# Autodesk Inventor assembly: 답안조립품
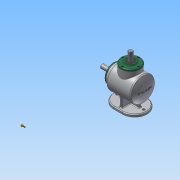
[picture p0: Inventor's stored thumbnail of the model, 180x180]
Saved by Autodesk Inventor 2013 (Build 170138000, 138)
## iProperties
Created: 2016-04
Part Number: 답안조립품
Document SubType Name: Assembly
Designer: Administrator
Author: Administrator
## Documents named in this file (14)
- C:\Users\Administrator\Desktop\460407V1006\답안조립품.iam
- C:\Users\Administrator\Desktop\460407V1006\M4.ipt
- C:\Users\Administrator\Desktop\460407V1006\메인 베벨기어.ipt
- C:\Users\Administrator\Desktop\460407V1006\메인 축.ipt
- 메인 축.ipt
- C:\Users\Administrator\Desktop\460407V1006\베어링 6203.ipt
- C:\Users\Administrator\Desktop\460407V1006\본체.ipt
- C:\Users\Administrator\Desktop\460407V1006\서브 베벨기어.ipt
- C:\Users\Administrator\Desktop\460407V1006\서브 축.ipt
- 서브 축.ipt
- C:\Users\Administrator\Desktop\460407V1006\오일실 17 32 8.ipt
- C:\Users\Administrator\Desktop\460407V1006\커버.ipt
- C:\Users\Administrator\Desktop\460407V1006\키 5x5.ipt
- C:\Users\Administrator\Desktop\460407V1006\키 4x4.ipt
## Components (1 placed, 1 different names)
1. M4:1
